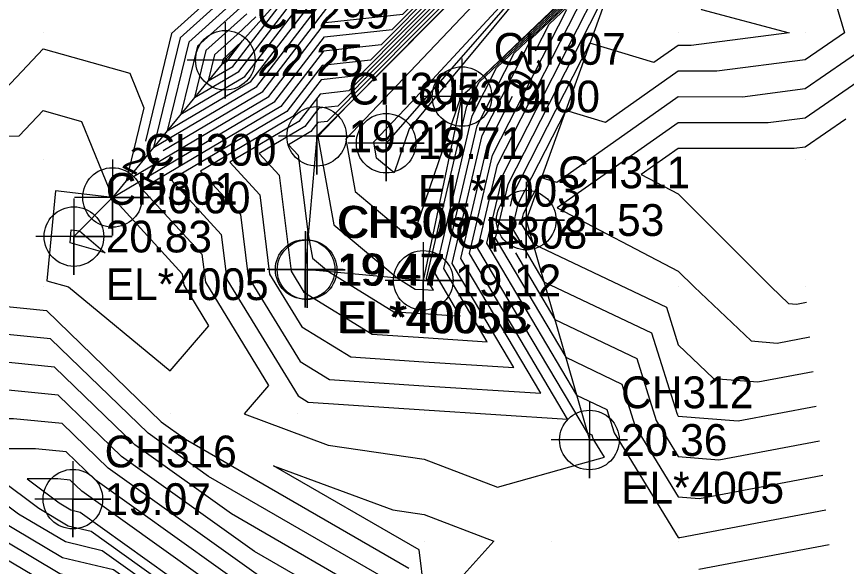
# Model space of a CAD drawing. Extents: x 2531902 to 2533249, y 715219 to 716099.
# Drawn here: x 2532967.9 to 2533033.2, y 715718 to 715761.3 of the extents above; entities that cross this region are included whole.
import ezdxf

# ---------------------------------------------------------------- set-up
doc = ezdxf.new("R2010")
doc.units = 0
for name, color, linetype in [('DTM Contours Major', 7, 'Continuous'), ('DTM Contours Major Text', 7, 'Continuous'), ('DTM Contours Minor', 7, 'Continuous'), ('Exist DTM Breakline', 7, 'Continuous'), ('Exist DTM Breakline Cogo Comment', 7, 'Continuous'), ('Exist DTM Breakline Cogo Elevation', 7, 'Continuous'), ('Exist DTM Breakline Cogo Number', 7, 'Continuous'), ('Exist DTM Breakline Cogo Point CELL', 7, 'Continuous'), ('Exist DTM Drainline', 7, 'Continuous'), ('Exist DTM Drainline Cogo Comment', 7, 'Continuous'), ('Exist DTM Drainline Cogo Elevation', 7, 'Continuous'), ('Exist DTM Drainline Cogo Number', 7, 'Continuous'), ('Exist DTM Drainline Cogo Point CELL', 7, 'Continuous'), ('Exist DTM QL2 LIDAR Elevation Point', 7, 'Continuous'), ('Exist DTM Regular Point CELL', 7, 'Continuous'), ('Exist DTM Regular Point Cogo Elevation', 7, 'Continuous'), ('Exist DTM Regular Point Cogo Number', 7, 'Continuous')]:
    doc.layers.add(name, color=color, linetype=linetype)

msp = doc.modelspace()

# ---------------------------------------------------------------- linework, layer by layer
at = {"layer": 'DTM Contours Major'}
for points in [[(2533008.764, 715758.562), (2533009.843, 715760.678), (2533014.663, 715765.254), (2533014.672, 715765.262), (2533023.159, 715773.32), (2533037.158, 715784.95), (2533037.66, 715785.451), (2533038.413, 715786.237), (2533049.753, 715797.548), (2533059.385, 715807.549), (2533072.253, 715820.374), (2533080.039, 715828.42)], [(2532979.452, 715750.737), (2532987.302, 715755.373), (2532992.336, 715761.936), (2532999.18, 715762.665), (2533004.55, 715768.086), (2533005.491, 715769.05), (2533005.991, 715769.568), (2533023.643, 715787.653), (2533026.693, 715790.807), (2533028.87, 715792.994), (2533029.024, 715793.143), (2533048.566, 715812.783), (2533050.214, 715814.379), (2533052.379, 715816.558)], [(2532977.504, 715809.832), (2532977.352, 715809.816), (2532973.798, 715801.389), (2532970.731, 715793.825), (2532968.124, 715787.575), (2532970, 715785.169), (2532977.166, 715790), (2532980, 715790.458), (2532980.764, 715790), (2532980, 715788.686), (2532972.904, 715780), (2532980, 715771.928), (2532985.876, 715774.124), (2532990, 715771.778), (2532991.063, 715771.063), (2532990.562, 715769.444), (2532989.08, 715768.02), (2532980.11, 715759.945), (2532978.063, 715751.479)], [(2533060.482, 715806.755), (2533042.787, 715788.38), (2533039.908, 715785.508), (2533038.536, 715784.076), (2533038.417, 715783.957), (2533025.075, 715772.872), (2533020.164, 715766.763), (2533021.834, 715761.834), (2533028.75, 715760), (2533021.01, 715758.99), (2533020, 715758.992), (2533018.095, 715757.652), (2533013.058, 715759.189), (2533006.986, 715747.286), (2533006.768, 715746.357)], [(2533006.472, 715764.984), (2533003.425, 715761.69), (2532993.835, 715751.621), (2532994.572, 715747.516), (2532999.056, 715743.739), (2533002.894, 715754.927), (2533003.116, 715755.194), (2533003.581, 715755.554), (2533013.979, 715765.427), (2533013.979, 715765.427), (2533033.397, 715783.864), (2533035.899, 715785.943), (2533036.784, 715786.825), (2533036.918, 715786.965), (2533046.121, 715796.145)], [(2533010.555, 715772.498), (2533007.237, 715769.099), (2533006.203, 715768.027), (2533005.772, 715767.585), (2532994.914, 715756.625), (2532991.892, 715756.303), (2532989.669, 715753.405), (2532982.4, 715749.112), (2532985.539, 715745.687), (2532986.15, 715740.796), (2532990.229, 715734.139), (2532992.557, 715732.707), (2532999.985, 715732.227), (2533009.18, 715731.631), (2533002.89, 715742.242), (2533004.978, 715751.14), (2533006.946, 715754.999)], [(2532984.936, 715757.342), (2532991.292, 715765.629), (2532989.621, 715764.023)], [(2532986.737, 715761.252), (2532985.29, 715759.862), (2532983.503, 715758.253), (2532983.007, 715756.202), (2532984.936, 715757.342)], [(2533007.186, 715742.667), (2533010.289, 715737.434), (2533016.734, 715734.372), (2533018.264, 715729.492), (2533020, 715726.65), (2533023.199, 715726.398), (2533031.125, 715727.897)], [(2532999.096, 715701.121), (2532997.844, 715709.449), (2532997.153, 715715.013), (2532984.824, 715722.135), (2532977.218, 715727.565), (2532970.886, 715733.691), (2532964.164, 715734.366), (2532953.147, 715734.365), (2532950.96, 715733.729), (2532949.152, 715733.616), (2532949.147, 715733.375), (2532949.48, 715730.826), (2532950.941, 715730.683), (2532952.799, 715730.294), (2532964.844, 715721.295), (2532971.314, 715717.455), (2532974.214, 715716.771)]]:
    msp.add_lwpolyline(points, dxfattribs=at)
at = {"layer": 'DTM Contours Minor'}
for points in [[(2533087.327, 715835.475), (2533082.204, 715828.012), (2533062.354, 715807.5), (2533061.434, 715806.583), (2533054.775, 715799.669), (2533042.737, 715786.408), (2533042.962, 715783.863), (2533040.204, 715782.579), (2533039.448, 715781.692), (2533033.848, 715773.848), (2533034.441, 715770), (2533037.497, 715767.497), (2533039.733, 715760), (2533030, 715753.287), (2533027.092, 715752.908), (2533020, 715752.921), (2533010.485, 715746.227), (2533020, 715741.25), (2533021.25, 715740), (2533025.743, 715735.743), (2533027.791, 715735.581), (2533030.365, 715736.068)], [(2533016.6, 715768.655), (2533011.353, 715766.712), (2533010.868, 715766.533), (2533009.843, 715765.74), (2532998.823, 715752.424), (2532997.639, 715748.973), (2532996.256, 715750.138), (2532996.029, 715751.404), (2532998.987, 715754.51), (2533010.27, 715766.707), (2533010.33, 715766.793), (2533010.564, 715767.143), (2533018.928, 715779.103), (2533029.337, 715789.864), (2533029.609, 715790.137), (2533030.835, 715791.328), (2533033.188, 715793.693), (2533052.341, 715812.246)], [(2532965.758, 715754.242), (2532970, 715758.737), (2532976.817, 715756.817), (2532977.934, 715754.092), (2532976.545, 715748.347), (2532987.776, 715754.98), (2532992.247, 715760.81), (2532998.327, 715761.457), (2533004.795, 715767.986), (2533005.634, 715768.845), (2533006.24, 715769.474), (2533022.026, 715785.648), (2533026.934, 715790.721), (2533028.937, 715792.734), (2533029.188, 715792.978), (2533047.168, 715811.047)], [(2532960, 715751.662), (2532968.121, 715751.879), (2532970, 715753.87), (2532973.02, 715753.02), (2532975.47, 715747.043), (2532975.468, 715747.038), (2532988.249, 715754.586), (2532992.158, 715759.683), (2532997.474, 715760.249), (2533005.039, 715767.885), (2533005.776, 715768.641), (2533006.489, 715769.38), (2533020.41, 715783.643), (2533027.174, 715790.636), (2533029.004, 715792.474), (2533029.353, 715792.813), (2533045.77, 715809.312)], [(2533035.984, 715797.164), (2533030.505, 715791.658), (2533029.474, 715790.657), (2533028.856, 715790.036), (2533009.095, 715769.606), (2533008.233, 715768.723), (2533006.773, 715767.209), (2533006.749, 715767.185), (2532993.991, 715754.306), (2532991.64, 715751.838), (2532992.888, 715744.893), (2532997.864, 715740.701), (2532999.285, 715739.827), (2532999.934, 715739.785), (2533000.738, 715739.733), (2533000.188, 715740.66), (2533003.371, 715754.223), (2533004.328, 715756.099), (2533014.116, 715765.392), (2533014.118, 715765.394), (2533031.349, 715781.755), (2533036.151, 715785.744)], [(2533037.914, 715784.354), (2533017.016, 715766.994), (2533015.088, 715765.162), (2533015.073, 715765.15), (2533013.979, 715764.112), (2533006.183, 715748.827), (2533004.916, 715743.428), (2533011.997, 715731.483), (2533014.396, 715730.343), (2533014.965, 715728.527), (2533020, 715720.286), (2533020.138, 715720.275), (2533031.631, 715722.45)], [(2533038.165, 715784.155), (2533016.248, 715765.948), (2533015.731, 715765.305), (2533016.12, 715764.158), (2533016.118, 715764.135), (2533014.965, 715764.487), (2533006.584, 715748.056), (2533005.591, 715743.824), (2533011.143, 715734.458), (2533015.565, 715732.358), (2533016.615, 715729.01), (2533020, 715723.468), (2533021.668, 715723.337), (2533031.378, 715725.174)], [(2533033.901, 715779.797), (2533024.597, 715768.222), (2533025.514, 715765.514), (2533030, 715764.325), (2533032.377, 715762.377), (2533033.087, 715760), (2533030, 715757.871), (2533023.038, 715756.962), (2533020, 715756.968), (2533014.272, 715752.939), (2533011.15, 715753.891), (2533007.388, 715746.515), (2533006.942, 715744.614), (2533009.434, 715740.41), (2533017.903, 715736.387), (2533019.913, 715729.975), (2533020, 715729.833), (2533024.729, 715729.459), (2533030.872, 715730.621)], [(2533005.283, 715767.785), (2532996.621, 715759.041), (2532992.07, 715758.556), (2532988.722, 715754.192), (2532977.777, 715747.728), (2532982.504, 715742.571), (2532982.78, 715740.36), (2532987.748, 715732.252), (2532985.821, 715730), (2532992.442, 715727.558), (2533000, 715726.437), (2533005.763, 715724.237), (2533012.303, 715726.086), (2533014.194, 715726.608), (2533013.316, 715728.045), (2533013.227, 715728.329), (2533012.852, 715728.507), (2533004.24, 715743.033), (2533005.781, 715749.598), (2533012.601, 715762.967)], [(2533005.527, 715767.685), (2532995.767, 715757.833), (2532991.981, 715757.43), (2532989.196, 715753.799), (2532980.088, 715748.42), (2532984.022, 715744.129), (2532984.465, 715740.578), (2532990.078, 715731.417), (2532990.875, 715730.926), (2532999.998, 715730.337), (2533011.291, 715729.605), (2533003.565, 715742.637), (2533005.379, 715750.369), (2533011.222, 715761.823)], [(2533006.016, 715767.485), (2532994.061, 715755.417), (2532991.803, 715755.177), (2532990.142, 715753.011), (2532984.711, 715749.804), (2532987.057, 715747.245), (2532987.834, 715741.014), (2532990.379, 715736.861), (2532994.239, 715734.487), (2532999.972, 715734.116), (2533007.07, 715733.656), (2533002.214, 715741.847), (2533004.576, 715751.911), (2533008.464, 715759.533), (2533014.526, 715765.289)], [(2533006.26, 715767.385), (2532993.208, 715754.209), (2532991.714, 715754.05), (2532990.615, 715752.618), (2532987.023, 715750.496), (2532988.574, 715748.803), (2532989.519, 715741.232), (2532990.53, 715739.583), (2532995.921, 715736.267), (2532999.96, 715736.006), (2533004.959, 715735.682), (2533001.539, 715741.451), (2533004.175, 715752.681), (2533007.086, 715758.389), (2533014.389, 715765.323)], [(2533006.504, 715767.285), (2532992.355, 715753.001), (2532991.625, 715752.924), (2532991.089, 715752.224), (2532989.334, 715751.188), (2532990.092, 715750.361), (2532990.869, 715744.135), (2532991.204, 715742.271), (2532992.471, 715741.204), (2532997.603, 715738.047), (2532999.947, 715737.896), (2533002.849, 715737.707), (2533000.864, 715741.056), (2533003.773, 715753.452), (2533005.707, 715757.244), (2533014.252, 715765.358)], [(2532988.322, 715766.388), (2532980.788, 715759.607), (2532978.699, 715750.965), (2532986.829, 715755.767), (2532992.425, 715763.063)], [(2532986.048, 715761.494), (2532982.824, 715758.591), (2532981.93, 715754.893), (2532985.409, 715756.948), (2532992.692, 715766.442)], [(2532986.806, 715763.125), (2532982.145, 715758.93), (2532980.853, 715753.584), (2532985.883, 715756.555), (2532992.603, 715765.316)], [(2532987.564, 715764.757), (2532981.467, 715759.268), (2532979.776, 715752.275), (2532986.356, 715756.161), (2532992.514, 715764.189)], [(2533036.41, 715760), (2533030, 715755.579), (2533025.065, 715754.935), (2533020, 715754.944), (2533010.449, 715748.225), (2533009.243, 715748.594), (2533007.789, 715745.744), (2533007.617, 715745.01), (2533008.58, 715743.385), (2533019.072, 715738.401), (2533020, 715735.441), (2533022.794, 715732.794), (2533026.26, 715732.52), (2533030.619, 715733.345)], [(2532984.463, 715757.736), (2532985.711, 715759.364), (2532984.532, 715758.231), (2532984.181, 715757.915), (2532984.084, 715757.512), (2532984.463, 715757.736)], [(2533033.208, 715753.208), (2533030, 715750.995), (2533029.12, 715750.88), (2533020, 715750.897), (2533017.078, 715748.841), (2533020, 715747.313), (2533027.312, 715740), (2533028.692, 715738.692), (2533029.321, 715738.642), (2533030.112, 715738.792)], [(2532980.986, 715741.013), (2532975.474, 715747.025), (2532975.465, 715747.034), (2532970.984, 715747.555), (2532970.297, 715740.484), (2532972.002, 715740), (2532980, 715733.382), (2532983.052, 715736.948), (2532981.095, 715740.142), (2532980.986, 715741.013)], [(2532972.221, 715744.481), (2532972.869, 715744.405), (2532974.895, 715742.671), (2532972.122, 715743.458), (2532972.221, 715744.481)], [(2532970.873, 715714.955), (2532961.635, 715720.437), (2532957.569, 715723.475), (2532950.438, 715724.968), (2532944.83, 715725.515), (2532943.553, 715735.302), (2532943.572, 715736.228), (2532950.511, 715736.661), (2532958.908, 715739.102), (2532960.664, 715739.102), (2532970.261, 715738.138), (2532979.304, 715729.39), (2532981.208, 715728.031), (2532998.787, 715717.876)], [(2532997.97, 715716.444), (2532983.016, 715725.083), (2532978.261, 715728.478), (2532970.573, 715735.915), (2532962.414, 715736.734), (2532956.027, 715736.733), (2532950.736, 715735.195), (2532946.362, 715734.922), (2532946.35, 715734.338), (2532947.155, 715728.17), (2532950.689, 715727.825), (2532955.184, 715726.884), (2532963.24, 715720.866), (2532971.094, 715716.205)], [(2532997.865, 715702.648), (2532996.879, 715709.202), (2532996.336, 715713.581), (2532986.632, 715719.187), (2532976.175, 715726.652), (2532971.198, 715731.468), (2532965.914, 715731.998), (2532952.698, 715731.996), (2532966.449, 715721.723), (2532971.535, 715718.705), (2532975.532, 715717.762), (2532987.752, 715709.005), (2532991.582, 715703.956), (2532997.865, 715702.648)], [(2532996.634, 715704.175), (2532995.915, 715708.955), (2532995.519, 715712.15), (2532988.44, 715716.238), (2532975.133, 715725.739), (2532971.51, 715729.244), (2532967.665, 715729.63), (2532958.046, 715729.629), (2532968.054, 715722.152), (2532971.755, 715719.956), (2532974.664, 715719.269), (2532989.257, 715708.811), (2532992.051, 715705.129), (2532996.634, 715704.175)], [(2532995.403, 715705.701), (2532994.951, 715708.709), (2532994.701, 715710.718), (2532990.249, 715713.29), (2532974.09, 715724.827), (2532971.822, 715727.021), (2532969.415, 715727.263), (2532963.393, 715727.262), (2532969.658, 715722.581), (2532971.976, 715721.206), (2532973.797, 715720.776), (2532990.762, 715708.618), (2532992.52, 715706.301), (2532995.403, 715705.701)], [(2532999.605, 715719.307), (2532988.14, 715725.93), (2532997.535, 715722.465), (2533000, 715722.099), (2533005.5, 715720), (2533002.884, 715717.116), (2533000, 715716.122), (2532999.605, 715719.307)], [(2532994.172, 715707.228), (2532993.987, 715708.462), (2532993.884, 715709.287), (2532992.057, 715710.342), (2532973.047, 715723.914), (2532972.134, 715724.797), (2532971.165, 715724.895), (2532968.74, 715724.894), (2532971.263, 715723.01), (2532972.196, 715722.456), (2532972.929, 715722.283), (2532992.268, 715708.425), (2532992.989, 715707.474), (2532994.172, 715707.228)], [(2533021.635, 715717.787), (2533031.884, 715719.727)]]:
    msp.add_lwpolyline(points, dxfattribs=at)
at = {"layer": 'Exist DTM Breakline'}
for points in [[(2533071.263, 715835.756), (2533026.299, 715790.948), (2533003.355, 715768.576), (2532992.757, 715767.273), (2532984.347, 715757.832), (2532975.467, 715747.036), (2532972.43, 715743.961)], [(2533073.808, 715833.204), (2533029.714, 715789.73), (2533006.807, 715767.161), (2532991.54, 715751.848), (2532990.629, 715741.375)], [(2533079.183, 715829.387), (2533035.625, 715786.159), (2533002.978, 715754.978), (2532999.93, 715740.509), (2532990.629, 715741.375)], [(2533082.767, 715827.756), (2533038.809, 715783.648), (2533015.193, 715765.12), (2533008.042, 715745.259), (2533013.01, 715727.955)]]:
    msp.add_lwpolyline(points, dxfattribs=at)
at = {"layer": 'Exist DTM Breakline Cogo Point CELL'}
for points in [[(2532984.347, 715760.832), (2532984.347, 715754.832), (2532984.347, 715757.832), (2532987.347, 715757.832), (2532981.347, 715757.832)], [(2533002.978, 715757.978), (2533002.978, 715751.978), (2533002.978, 715754.978), (2533005.978, 715754.978), (2532999.978, 715754.978)], [(2532991.54, 715754.848), (2532991.54, 715748.848), (2532991.54, 715751.848), (2532994.54, 715751.848), (2532988.54, 715751.848)], [(2532975.467, 715750.036), (2532975.467, 715744.036), (2532975.467, 715747.036), (2532978.467, 715747.036), (2532972.467, 715747.036)], [(2533008.042, 715748.259), (2533008.042, 715742.259), (2533008.042, 715745.259), (2533011.042, 715745.259), (2533005.042, 715745.259)], [(2532972.43, 715746.961), (2532972.43, 715740.961), (2532972.43, 715743.961), (2532975.43, 715743.961), (2532969.43, 715743.961)], [(2532990.629, 715744.375), (2532990.629, 715738.375), (2532990.629, 715741.375), (2532993.629, 715741.375), (2532987.629, 715741.375)], [(2532990.784, 715744.347), (2532990.784, 715738.347), (2532990.784, 715741.347), (2532993.784, 715741.347), (2532987.784, 715741.347)], [(2532999.93, 715743.509), (2532999.93, 715737.509), (2532999.93, 715740.509), (2533002.93, 715740.509), (2532996.93, 715740.509)], [(2533013.01, 715730.955), (2533013.01, 715724.955), (2533013.01, 715727.955), (2533016.01, 715727.955), (2533010.01, 715727.955)]]:
    msp.add_lwpolyline(points, dxfattribs=at)
for centre in [(2532984.347, 715757.832), (2533002.978, 715754.978), (2532991.54, 715751.848), (2532975.467, 715747.036), (2533008.042, 715745.259), (2532972.43, 715743.961), (2532990.629, 715741.375), (2532990.784, 715741.347), (2532999.93, 715740.509), (2533013.01, 715727.955)]:
    msp.add_circle(centre, 2.344, dxfattribs=at)
at = {"layer": 'Exist DTM Drainline'}
msp.add_lwpolyline([(2533077.016, 715831.416), (2533032.437, 715787.738), (2533010.445, 715766.684), (2532997.007, 715751.307)], dxfattribs=at)
at = {"layer": 'Exist DTM Drainline Cogo Point CELL'}
msp.add_lwpolyline([(2532997.007, 715754.307), (2532997.007, 715748.307), (2532997.007, 715751.307), (2533000.007, 715751.307), (2532994.007, 715751.307)], dxfattribs=at)
msp.add_circle((2532997.007, 715751.307), 2.344, dxfattribs=at)
at = {"layer": 'Exist DTM QL2 LIDAR Elevation Point'}
for p, q in [((2532970, 715760), (2532970, 715760)), ((2532980, 715760), (2532980, 715760)), ((2533020, 715760), (2533020, 715760)), ((2533030, 715760), (2533030, 715760)), ((2532970, 715750), (2532970, 715750)), ((2533020, 715750), (2533020, 715750)), ((2533030, 715750), (2533030, 715750)), ((2532970, 715740), (2532970, 715740)), ((2532980, 715740), (2532980, 715740)), ((2533020, 715740), (2533020, 715740)), ((2533030, 715740), (2533030, 715740)), ((2532980, 715730), (2532980, 715730)), ((2532990, 715730), (2532990, 715730)), ((2533000, 715730), (2533000, 715730)), ((2533020, 715730), (2533020, 715730)), ((2533000, 715720), (2533000, 715720)), ((2533010, 715720), (2533010, 715720)), ((2533020, 715720), (2533020, 715720))]:
    msp.add_line(p, q, dxfattribs=at)
at = {"layer": 'Exist DTM Regular Point CELL'}
msp.add_lwpolyline([(2532972.345, 715726.299), (2532972.345, 715720.299), (2532972.345, 715723.299), (2532975.345, 715723.299), (2532969.345, 715723.299)], dxfattribs=at)
msp.add_circle((2532972.345, 715723.299), 2.344, dxfattribs=at)

# ---------------------------------------------------------------- texts
at = {"layer": 'DTM Contours Major Text'}
for s, rotation, p in [('20', 242.97454, (2533007.705, 715758.686)), ('21', 331.88229, (2532976.119, 715749.446)), ('21', 276.46463, (2533005.172, 715745.58))]:
    msp.add_text(s, height=2, rotation=rotation, dxfattribs=at).set_placement(p)
at = {"layer": 'Exist DTM Breakline Cogo Comment'}
for s, p in [('EL*4005', (2532974.93, 715738.961)), ('EL*4005B', (2532993.129, 715736.375)), ('EL*4005C', (2532993.284, 715736.347)), ('EL*4005', (2533015.51, 715722.955))]:
    msp.add_text(s, height=2.5, dxfattribs=at).set_placement(p)
at = {"layer": 'Exist DTM Breakline Cogo Elevation'}
for s, p in [('22.25', (2532986.847, 715756.582)), ('19.00', (2533005.478, 715753.728)), ('19.21', (2532994.04, 715750.598)), ('20.60', (2532977.967, 715745.786)), ('21.53', (2533010.542, 715744.009)), ('20.83', (2532974.93, 715742.711)), ('19.47', (2532993.129, 715740.125)), ('19.47', (2532993.284, 715740.097)), ('19.12', (2533002.43, 715739.259)), ('20.36', (2533015.51, 715726.705))]:
    msp.add_text(s, height=2.5, dxfattribs=at).set_placement(p)
at = {"layer": 'Exist DTM Breakline Cogo Number'}
for s, p in [('CH299', (2532986.847, 715760.332)), ('CH307', (2533005.478, 715757.478)), ('CH305', (2532994.04, 715754.348)), ('CH300', (2532977.967, 715749.536)), ('CH311', (2533010.542, 715747.759)), ('CH301', (2532974.93, 715746.461)), ('CH306', (2532993.129, 715743.875)), ('CH309', (2532993.284, 715743.847)), ('CH308', (2533002.43, 715743.009)), ('CH312', (2533015.51, 715730.455))]:
    msp.add_text(s, height=2.5, dxfattribs=at).set_placement(p)
at = {"layer": 'Exist DTM Drainline Cogo Comment'}
msp.add_text('EL*4003', height=2.5, dxfattribs=at).set_placement((2532999.507, 715746.307))
at = {"layer": 'Exist DTM Drainline Cogo Elevation'}
msp.add_text('18.71', height=2.5, dxfattribs=at).set_placement((2532999.507, 715750.057))
at = {"layer": 'Exist DTM Drainline Cogo Number'}
msp.add_text('CH304', height=2.5, dxfattribs=at).set_placement((2532999.507, 715753.807))
at = {"layer": 'Exist DTM Regular Point Cogo Elevation'}
msp.add_text('19.07', height=2.5, dxfattribs=at).set_placement((2532974.845, 715722.049))
at = {"layer": 'Exist DTM Regular Point Cogo Number'}
msp.add_text('CH316', height=2.5, dxfattribs=at).set_placement((2532974.845, 715725.799))

doc.saveas('drawing.dxf')
